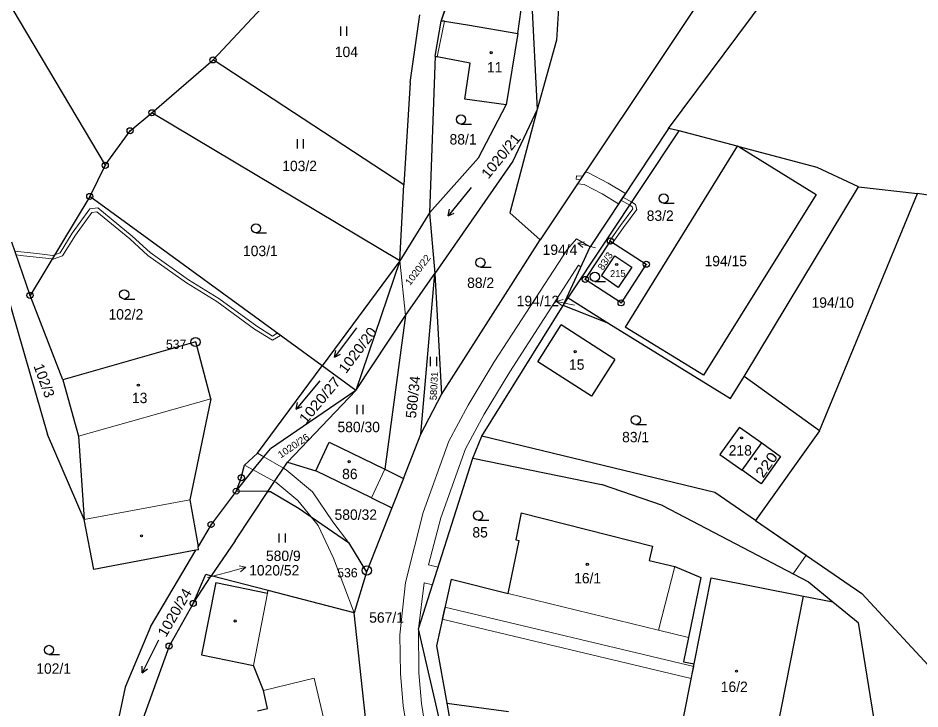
# Model space of a CAD drawing. Extents: x -601131 to -597152, y -1058536 to -1055911.
# Drawn here: x -599499.1 to -599351.3, y -1056861.6 to -1056748.4 of the extents above; entities that cross this region are included whole.
import ezdxf
from ezdxf.enums import TextEntityAlignment as Align

# ---------------------------------------------------------------- set-up
doc = ezdxf.new("R2010")
doc.units = 0
doc.header["$LTSCALE"] = 0.68
for name, color, linetype, lineweight in [('1', 7, 'Continuous', 25), ('13', 7, 'Continuous', 13), ('3', 7, 'Continuous', 25), ('4', 7, 'Continuous', 13), ('5', 7, 'Continuous', 25), ('7', 7, 'Continuous', 13), ('8', 7, 'Continuous', 25)]:
    doc.layers.add(name, color=color, linetype=linetype, lineweight=lineweight)
doc.layers.add('2', color=7, linetype='Continuous')

msp = doc.modelspace()

# ---------------------------------------------------------------- linework, layer by layer
at = {"layer": '1'}
for p, q in [((-599551.94, -1056659.38), (-599484.78, -1056772.53)), ((-599371.62, -1056721.87), (-599413.52, -1056784.73)), ((-599429.72, -1056748.92), (-599425.35, -1056734.91)), ((-599417.21, -1056750.96), (-599415.29, -1056737.38)), ((-599415.29, -1056737.38), (-599414.02, -1056763.41)), ((-599467.12, -1056755.26), (-599452.95, -1056740.08)), ((-599392.52, -1056766.52), (-599372.87, -1056740.17)), ((-599429.72, -1056748.92), (-599427.64, -1056742.94)), ((-599410.27, -1056742.24), (-599410.86, -1056752.01)), ((-599434.8, -1056758.96), (-599433.23, -1056747.88)), ((-599430.75, -1056754.64), (-599429.72, -1056748.92)), ((-599429.22, -1056748.92), (-599429.72, -1056748.92)), ((-599429.22, -1056748.92), (-599425.44, -1056749.51)), ((-599425.44, -1056749.51), (-599417.21, -1056750.96)), ((-599417.21, -1056750.96), (-599419.08, -1056762.64)), ((-599410.86, -1056752.01), (-599414.02, -1056763.41)), ((-599477.13, -1056763.92), (-599467.12, -1056755.26)), ((-599435.85, -1056775.73), (-599467.12, -1056755.26)), ((-599430.75, -1056754.64), (-599431.65, -1056780.31)), ((-599430.75, -1056754.64), (-599430.42, -1056754.74)), ((-599425, -1056755.8), (-599430.42, -1056754.74)), ((-599425.85, -1056761.7), (-599425, -1056755.8)), ((-599434.8, -1056758.96), (-599435.85, -1056775.73)), ((-599419.08, -1056762.64), (-599425.85, -1056761.7)), ((-599423.64, -1056771.32), (-599419.08, -1056762.64)), ((-599480.7, -1056766.87), (-599477.13, -1056763.92)), ((-599436.52, -1056788.17), (-599477.13, -1056763.92)), ((-599414.02, -1056763.41), (-599418.48, -1056780.32)), ((-599414.02, -1056763.41), (-599418.03, -1056771.83)), ((-599484.78, -1056772.53), (-599480.7, -1056766.87)), ((-599408.96, -1056794.27), (-599390.76, -1056766.89)), ((-599392.52, -1056766.52), (-599405.35, -1056785.88)), ((-599390.76, -1056766.89), (-599392.52, -1056766.52)), ((-599381.23, -1056769.41), (-599399.61, -1056799.07)), ((-599380.92, -1056769.49), (-599368.31, -1056777.29)), ((-599368.15, -1056772.87), (-599380.92, -1056769.49)), ((-599431.65, -1056780.31), (-599423.64, -1056771.32)), ((-599484.78, -1056772.53), (-599487.31, -1056777.64)), ((-599418.03, -1056771.83), (-599430.78, -1056790.24)), ((-599361.35, -1056776.07), (-599368.15, -1056772.87)), ((-599436.52, -1056788.17), (-599435.85, -1056775.73)), ((-599368.31, -1056777.29), (-599386.76, -1056806.92)), ((-599380.09, -1056807.12), (-599361.35, -1056776.07)), ((-599367.78, -1056816.02), (-599351.73, -1056777.15)), ((-599361.35, -1056776.07), (-599351.73, -1056777.15)), ((-599327.76, -1056781.06), (-599351.73, -1056777.15)), ((-599487.31, -1056777.64), (-599497.1, -1056793.85)), ((-599449.25, -1056805.4), (-599487.31, -1056777.64)), ((-599431.65, -1056780.31), (-599436.52, -1056788.17)), ((-599431.65, -1056780.31), (-599430.78, -1056790.24)), ((-599413.52, -1056784.73), (-599418.48, -1056780.32)), ((-599429.67, -1056810.07), (-599413.52, -1056784.73)), ((-599497.1, -1056793.85), (-599500.08, -1056785.1)), ((-599409.73, -1056795.49), (-599405.35, -1056785.88)), ((-599406.13, -1056791.23), (-599402.01, -1056784.94)), ((-599402.01, -1056784.94), (-599396.14, -1056788.74)), ((-599436.52, -1056788.17), (-599449.25, -1056805.4)), ((-599436.52, -1056788.17), (-599443.7, -1056809.45)), ((-599398.5, -1056789.24), (-599400.72, -1056792.53)), ((-599396.14, -1056788.74), (-599400.26, -1056795.07)), ((-599435.58, -1056797.13), (-599430.78, -1056790.24)), ((-599433.05, -1056816.57), (-599430.78, -1056790.24)), ((-599430.78, -1056790.24), (-599429.67, -1056810.07)), ((-599400.26, -1056795.07), (-599406.13, -1056791.23)), ((-599501.07, -1056792.92), (-599494.25, -1056816.67)), ((-599491.72, -1056807.67), (-599497.1, -1056793.85)), ((-599409.73, -1056795.49), (-599408.96, -1056794.27)), ((-599408.96, -1056794.27), (-599402.25, -1056798.43)), ((-599423.06, -1056816.9), (-599409.73, -1056795.49)), ((-599402.25, -1056798.43), (-599409.73, -1056795.49)), ((-599443.7, -1056809.45), (-599435.58, -1056797.13)), ((-599435.58, -1056797.13), (-599439, -1056822.33)), ((-599413.91, -1056804.75), (-599410.1, -1056798.68)), ((-599401.3, -1056804.33), (-599410.1, -1056798.68)), ((-599402.25, -1056798.43), (-599382.36, -1056810.74)), ((-599386.76, -1056806.92), (-599399.61, -1056799.07)), ((-599469.95, -1056801.48), (-599491.72, -1056807.67)), ((-599467.5, -1056810.78), (-599469.95, -1056801.48)), ((-599459.81, -1056819.7), (-599449.25, -1056805.4)), ((-599443.7, -1056809.45), (-599449.25, -1056805.4)), ((-599405.13, -1056810.34), (-599413.91, -1056804.75)), ((-599401.3, -1056804.33), (-599405.13, -1056810.34)), ((-599491.72, -1056807.67), (-599489.16, -1056816.94)), ((-599382.36, -1056810.74), (-599380.09, -1056807.12)), ((-599367.78, -1056816.02), (-599380.09, -1056807.12)), ((-599443.7, -1056809.45), (-599457.68, -1056818.97)), ((-599443.7, -1056809.45), (-599454.94, -1056821.19)), ((-599467.5, -1056810.78), (-599470.92, -1056827.35)), ((-599433.05, -1056816.57), (-599429.67, -1056810.07)), ((-599380.86, -1056815.42), (-599384.07, -1056819.9)), ((-599380.86, -1056815.42), (-599377.23, -1056818.03)), ((-599488.25, -1056830.58), (-599494.25, -1056816.67)), ((-599489.16, -1056816.94), (-599488.25, -1056830.58)), ((-599435.92, -1056823.84), (-599433.05, -1056816.57)), ((-599424.56, -1056820.53), (-599423.06, -1056816.9)), ((-599384.89, -1056826.15), (-599423.06, -1056816.9)), ((-599367.78, -1056816.02), (-599378.25, -1056830.74)), ((-599450.26, -1056822.59), (-599448.07, -1056817.88)), ((-599448.07, -1056817.88), (-599439, -1056822.33)), ((-599377.23, -1056818.03), (-599374.16, -1056820.24)), ((-599461.96, -1056821.68), (-599459.81, -1056819.7)), ((-599460.52, -1056822.46), (-599458.77, -1056820.31)), ((-599458.77, -1056820.31), (-599457.68, -1056818.97)), ((-599384.07, -1056819.9), (-599380.42, -1056822.5)), ((-599462.49, -1056823.71), (-599461.96, -1056821.68)), ((-599455.6, -1056822.18), (-599454.94, -1056821.19)), ((-599454.94, -1056821.19), (-599450.26, -1056822.59)), ((-599433.46, -1056848.51), (-599424.56, -1056820.53)), ((-599424.56, -1056820.53), (-599403.47, -1056824.84)), ((-599463.33, -1056825.93), (-599460.52, -1056822.46)), ((-599457.04, -1056824.35), (-599455.6, -1056822.18)), ((-599441.15, -1056827.03), (-599450.26, -1056822.59)), ((-599439, -1056822.33), (-599435.92, -1056823.84)), ((-599462.49, -1056823.71), (-599463.33, -1056825.93)), ((-599458.14, -1056826), (-599457.04, -1056824.35)), ((-599435.92, -1056823.84), (-599437.83, -1056828.65)), ((-599463.33, -1056825.93), (-599467.43, -1056831.39)), ((-599463.51, -1056834.09), (-599458.14, -1056826)), ((-599458.14, -1056826), (-599463.33, -1056825.93)), ((-599458.14, -1056826), (-599457.68, -1056826.01)), ((-599457.68, -1056826.01), (-599453.02, -1056828.76)), ((-599393.47, -1056828.27), (-599403.47, -1056824.84)), ((-599378.25, -1056830.74), (-599384.89, -1056826.15)), ((-599470.92, -1056827.35), (-599469.58, -1056835.02)), ((-599441.15, -1056827.03), (-599437.83, -1056828.65)), ((-599453.02, -1056828.76), (-599451.06, -1056830.11)), ((-599437.83, -1056828.65), (-599442, -1056839.21)), ((-599393.47, -1056828.27), (-599369.55, -1056840.81)), ((-599486.66, -1056838.75), (-599488.25, -1056830.58)), ((-599451.06, -1056830.11), (-599444.93, -1056834.36)), ((-599416.62, -1056829.48), (-599417.51, -1056833.91)), ((-599416.62, -1056829.48), (-599395.11, -1056834.93)), ((-599467.43, -1056831.39), (-599469.58, -1056835.02)), ((-599378.25, -1056830.74), (-599360.82, -1056842.71)), ((-599469.49, -1056835.54), (-599469.58, -1056835.02)), ((-599463.51, -1056834.09), (-599467.42, -1056839.8)), ((-599444.93, -1056834.36), (-599442, -1056839.21)), ((-599418.78, -1056842.69), (-599416.95, -1056834.02)), ((-599417.51, -1056833.91), (-599416.95, -1056834.02)), ((-599395.11, -1056834.93), (-599395.66, -1056837.27)), ((-599469.94, -1056835.62), (-599486.66, -1056838.75)), ((-599477.37, -1056848.16), (-599469.94, -1056835.62)), ((-599469.49, -1056835.54), (-599469.94, -1056835.62)), ((-599395.66, -1056837.27), (-599391.44, -1056838.26)), ((-599470.36, -1056844.32), (-599468.28, -1056839.51)), ((-599468.28, -1056839.51), (-599467.42, -1056839.8)), ((-599442, -1056839.21), (-599443.98, -1056845.84)), ((-599391.44, -1056838.26), (-599387.21, -1056840.08)), ((-599470.36, -1056844.32), (-599467.42, -1056839.8)), ((-599466.66, -1056840.89), (-599468.99, -1056852.74)), ((-599458.1, -1056842.2), (-599467.42, -1056839.8)), ((-599466.66, -1056840.89), (-599458.19, -1056842.66)), ((-599428.13, -1056840.35), (-599430.53, -1056851.27)), ((-599428.13, -1056840.35), (-599418.78, -1056842.69)), ((-599387.21, -1056840.08), (-599389.22, -1056849.88)), ((-599388.28, -1056854.23), (-599385.49, -1056840.15)), ((-599385.49, -1056840.15), (-599370.36, -1056843.12)), ((-599369.55, -1056840.81), (-599365.59, -1056844.06)), ((-599458.19, -1056842.66), (-599458.1, -1056842.2)), ((-599443.98, -1056845.84), (-599458.1, -1056842.2)), ((-599375.51, -1056869.1), (-599370.36, -1056843.12)), ((-599345.66, -1056859.14), (-599360.82, -1056842.71)), ((-599470.36, -1056844.32), (-599474.31, -1056851.31)), ((-599441.71, -1056867.16), (-599443.98, -1056845.84)), ((-599477.37, -1056848.16), (-599481.51, -1056858.06)), ((-599361.42, -1056847.47), (-599358.35, -1056866.66)), ((-599420.11, -1056905.82), (-599433.46, -1056848.51)), ((-599389.22, -1056849.88), (-599390.05, -1056853.89)), ((-599474.31, -1056851.31), (-599479.03, -1056864.47)), ((-599430.53, -1056851.27), (-599428.83, -1056860.65)), ((-599468.99, -1056852.74), (-599460.51, -1056854.48)), ((-599390.58, -1056865.84), (-599388.28, -1056854.23)), ((-599390.05, -1056853.89), (-599388.28, -1056854.23)), ((-599458.83, -1056858.57), (-599460.51, -1056854.48)), ((-599481.51, -1056858.06), (-599483.14, -1056865.86)), ((-599458.17, -1056861.55), (-599458.83, -1056858.57)), ((-599459.85, -1056861.92), (-599458.17, -1056861.55)), ((-599428.83, -1056860.65), (-599418.74, -1056862.02)), ((-599428.83, -1056860.65), (-599426.94, -1056871.04))]:
    msp.add_line(p, q, dxfattribs=at)
for points in [[(-599380.92, -1056769.49), (-599381.23, -1056769.41), (-599390.76, -1056766.89)], [(-599400.72, -1056792.53), (-599403.49, -1056790.67), (-599401.28, -1056787.37), (-599398.5, -1056789.24)], [(-599374.16, -1056820.24), (-599377.34, -1056824.7), (-599380.42, -1056822.5), (-599377.23, -1056818.03)], [(-599370.36, -1056843.12), (-599365.59, -1056844.06), (-599361.42, -1056847.47)]]:
    msp.add_lwpolyline(points, dxfattribs=at)
at = {"layer": '13'}
for points in [[(-599407.65, -1056774.83), (-599406.97, -1056774.9), (-599406.59, -1056774.33), (-599407.59, -1056774.23)], [(-599406.15, -1056773.67), (-599406.59, -1056774.33), (-599406.97, -1056774.9), (-599407.41, -1056775.56), (-599406.32, -1056775.67), (-599403.37, -1056777.19), (-599400.68, -1056778.83), (-599400.29, -1056778.25), (-599399.96, -1056777.75), (-599399.57, -1056777.16), (-599402.39, -1056775.45), (-599405.74, -1056773.71)], [(-599399.88, -1056782.75), (-599397.69, -1056779.76), (-599397.92, -1056778.93), (-599398.53, -1056778.58), (-599399.96, -1056777.75), (-599400.29, -1056778.25), (-599398.86, -1056779.08), (-599398.44, -1056779.33), (-599398.35, -1056779.64), (-599400.36, -1056782.39), (-599402.18, -1056784.96), (-599402.08, -1056785.05), (-599402.01, -1056784.94), (-599401.61, -1056785.2)], [(-599402.03, -1056785.43), (-599401.86, -1056785.24), (-599401.73, -1056785.36), (-599401.61, -1056785.2), (-599402.01, -1056784.94), (-599402.08, -1056785.05), (-599402.22, -1056785.26)], [(-599423.06, -1056816.9), (-599424.56, -1056820.53), (-599403.47, -1056824.84), (-599393.47, -1056828.27), (-599372.06, -1056839.49), (-599369.96, -1056836.43), (-599378.25, -1056830.74), (-599384.89, -1056826.15)], [(-599429.13, -1056844.92), (-599429.56, -1056846.88), (-599388.76, -1056856.63), (-599388.37, -1056854.67)]]:
    msp.add_lwpolyline(points, close=True, dxfattribs=at)
for points in [[(-599499.36, -1056787.22), (-599498.64, -1056787.29), (-599496.07, -1056787.6), (-599493.49, -1056787.88), (-599493.3, -1056787.91), (-599491.77, -1056787.36), (-599489.67, -1056784), (-599486.95, -1056780.25), (-599486.16, -1056780.14), (-599480.76, -1056784.6), (-599477.81, -1056787.3), (-599471.48, -1056791.81), (-599466.49, -1056794.86), (-599460.31, -1056799.4), (-599457.36, -1056801.21), (-599456.09, -1056800.41), (-599456.61, -1056800.03), (-599457.36, -1056800.51), (-599459.97, -1056798.9), (-599466.15, -1056794.36), (-599471.14, -1056791.31), (-599477.43, -1056786.84), (-599480.36, -1056784.14), (-599485.98, -1056779.5), (-599487.29, -1056779.69), (-599490.17, -1056783.66), (-599492.17, -1056786.86), (-599493.08, -1056787.19), (-599493.38, -1056787.29), (-599496.01, -1056787), (-599498.58, -1056786.69), (-599499.57, -1056786.59)], [(-599431.63, -1056868.93), (-599432.99, -1056860.71), (-599433.42, -1056855.68), (-599433.46, -1056848.51), (-599432.51, -1056840.94), (-599431.15, -1056841.26), (-599430.24, -1056838.4), (-599431.81, -1056838.02), (-599429.82, -1056830.3), (-599425.77, -1056818.98), (-599422.72, -1056813.3), (-599418.52, -1056806.35), (-599407.24, -1056788.92), (-599406.85, -1056789.18), (-599405.35, -1056785.88), (-599407.59, -1056784.59), (-599409.06, -1056786.25), (-599421.06, -1056804.76), (-599425.32, -1056811.82), (-599428.51, -1056817.76), (-599432.69, -1056829.41), (-599435.59, -1056840.9), (-599436.51, -1056849.45), (-599436.42, -1056855.83), (-599435.97, -1056861.08), (-599434.58, -1056869.5)]]:
    msp.add_lwpolyline(points, dxfattribs=at)
at = {"layer": '3'}
for p, q in [((-599446.181, -1056751.3), (-599446.181, -1056749.8)), ((-599445.18, -1056751.3), (-599445.18, -1056749.8)), ((-599426.503, -1056765.78), (-599424.753, -1056765.78)), ((-599453.301, -1056769.77), (-599453.301, -1056768.27)), ((-599452.3, -1056769.77), (-599452.3, -1056768.27)), ((-599393.303, -1056778.73), (-599391.553, -1056778.73)), ((-599428.595, -1056780.809), (-599428.37, -1056779.734)), ((-599460.083, -1056783.6), (-599458.333, -1056783.6)), ((-599423.313, -1056789.22), (-599421.563, -1056789.22)), ((-599404.573, -1056791.56), (-599402.823, -1056791.56)), ((-599481.683, -1056794.44), (-599479.933, -1056794.44)), ((-599447.213, -1056803.954), (-599447.025, -1056802.872)), ((-599431.471, -1056805.43), (-599431.471, -1056803.93)), ((-599430.47, -1056805.43), (-599430.47, -1056803.93)), ((-599453.506, -1056812.466), (-599453.262, -1056811.395)), ((-599443.511, -1056813.29), (-599443.511, -1056811.79)), ((-599442.51, -1056813.29), (-599442.51, -1056811.79)), ((-599397.853, -1056815.01), (-599396.103, -1056815.01)), ((-599423.693, -1056830.67), (-599421.943, -1056830.67)), ((-599456.271, -1056834.34), (-599456.271, -1056832.84)), ((-599455.27, -1056834.34), (-599455.27, -1056832.84)), ((-599494.003, -1056852.69), (-599492.253, -1056852.69)), ((-599478.71, -1056855.718), (-599478.733, -1056854.62))]:
    msp.add_line(p, q, dxfattribs=at)
for points in [[(-599424.819, -1056776.146), (-599428.595, -1056780.809), (-599427.591, -1056780.366)], [(-599443.602, -1056799.163), (-599447.213, -1056803.954), (-599446.224, -1056803.476)], [(-599449.649, -1056807.869), (-599453.506, -1056812.466), (-599452.494, -1056812.04)], [(-599476.08, -1056850.325), (-599478.71, -1056855.718), (-599477.831, -1056855.06)]]:
    msp.add_lwpolyline(points, dxfattribs=at)
for centre in [(-599426.5029, -1056765.0298), (-599393.3029, -1056777.9798), (-599460.0829, -1056782.8498), (-599423.3129, -1056788.4698), (-599404.5729, -1056790.8098), (-599481.6829, -1056793.6898), (-599397.8529, -1056814.2598), (-599423.6929, -1056829.9198), (-599494.0029, -1056851.9398)]:
    msp.add_circle(centre, 0.75, dxfattribs=at)
at = {"layer": '4'}
for p, q in [((-599430.42, -1056754.74), (-599429.22, -1056748.92)), ((-599381.23, -1056769.41), (-599381.18, -1056769.32)), ((-599381.18, -1056769.32), (-599380.92, -1056769.49)), ((-599435.58, -1056797.13), (-599436.52, -1056788.17)), ((-599489.16, -1056816.94), (-599467.5, -1056810.78)), ((-599458.77, -1056820.31), (-599459.81, -1056819.7)), ((-599455.6, -1056822.18), (-599458.77, -1056820.31)), ((-599460.52, -1056822.46), (-599461.96, -1056821.68)), ((-599457.04, -1056824.35), (-599460.52, -1056822.46)), ((-599455.15, -1056822.44), (-599455.6, -1056822.18)), ((-599450.8, -1056826.05), (-599455.15, -1056822.44)), ((-599441.15, -1056827.03), (-599439, -1056822.33)), ((-599456.81, -1056824.47), (-599457.04, -1056824.35)), ((-599456.81, -1056824.47), (-599453.24, -1056827.48)), ((-599447.47, -1056830.97), (-599450.8, -1056826.05)), ((-599488.25, -1056830.58), (-599470.92, -1056827.35)), ((-599453.24, -1056827.48), (-599451.06, -1056830.11)), ((-599451.06, -1056830.11), (-599449.87, -1056831.56)), ((-599449.87, -1056831.56), (-599447.39, -1056836.89)), ((-599444.93, -1056834.36), (-599447.47, -1056830.97)), ((-599447.39, -1056836.89), (-599443.98, -1056845.84)), ((-599394.15, -1056848.68), (-599391.44, -1056838.26)), ((-599460.51, -1056854.48), (-599458.19, -1056842.66)), ((-599418.78, -1056842.69), (-599394.15, -1056848.68)), ((-599394.15, -1056848.68), (-599389.22, -1056849.88)), ((-599450.55, -1056856.58), (-599458.83, -1056858.57)), ((-599447.77, -1056868.39), (-599450.55, -1056856.58))]:
    msp.add_line(p, q, dxfattribs=at)
at = {"layer": '5'}
for centre in [(-599421.5468, -1056754.0692), (-599400.9868, -1056788.7792), (-599407.7868, -1056803.0692), (-599479.3468, -1056808.5492), (-599380.5268, -1056817.1892), (-599444.8068, -1056821.0992), (-599378.2468, -1056820.6292), (-599478.8368, -1056833.2492), (-599405.8068, -1056837.9192), (-599463.4968, -1056847.1992), (-599381.3668, -1056855.4192)]:
    msp.add_circle(centre, 0.175, dxfattribs=at)
at = {"layer": '7'}
for p, q in [((-599407.359, -1056785.283), (-599406.521, -1056786.026)), ((-599410.855, -1056794.826), (-599409.98, -1056795.524)), ((-599461.761, -1056838.403), (-599462.858, -1056838.179))]:
    msp.add_line(p, q, dxfattribs=at)
for points in [[(-599404.46, -1056786.06), (-599407.359, -1056785.283), (-599406.262, -1056785.059)], [(-599407.92, -1056795.45), (-599410.855, -1056794.826), (-599409.772, -1056794.544)], [(-599468.02, -1056840.07), (-599464.66, -1056839.18), (-599461.761, -1056838.403), (-599462.599, -1056839.146)]]:
    msp.add_lwpolyline(points, dxfattribs=at)
at = {"layer": '8'}
for centre, radius in [((-599467.12, -1056755.2599), 0.5), ((-599467.12, -1056755.2599), 0.0303), ((-599477.13, -1056763.9199), 0.5), ((-599477.13, -1056763.9199), 0.0303), ((-599480.7, -1056766.8699), 0.5), ((-599480.7, -1056766.8699), 0.0303), ((-599484.78, -1056772.5299), 0.5), ((-599484.78, -1056772.5299), 0.0303), ((-599487.31, -1056777.6399), 0.5), ((-599487.31, -1056777.6399), 0.0303), ((-599402.01, -1056784.9399), 0.5), ((-599402.01, -1056784.9399), 0.0303), ((-599396.14, -1056788.7399), 0.5), ((-599396.14, -1056788.7399), 0.0303), ((-599406.13, -1056791.2299), 0.5), ((-599406.13, -1056791.2299), 0.0303), ((-599497.1, -1056793.8499), 0.5), ((-599497.1, -1056793.8499), 0.0303), ((-599400.26, -1056795.0699), 0.5), ((-599400.26, -1056795.0699), 0.0303), ((-599469.99, -1056801.4998), 0.75), ((-599469.99, -1056801.4998), 0.03), ((-599462.49, -1056823.7099), 0.5), ((-599462.49, -1056823.7099), 0.0303), ((-599463.33, -1056825.9299), 0.5), ((-599463.33, -1056825.9299), 0.0303), ((-599467.43, -1056831.3899), 0.5), ((-599467.43, -1056831.3899), 0.0303), ((-599441.93, -1056838.9298), 0.75), ((-599441.93, -1056838.9298), 0.03), ((-599470.36, -1056844.3199), 0.5), ((-599470.36, -1056844.3199), 0.0303), ((-599474.31, -1056851.3099), 0.5), ((-599474.31, -1056851.3099), 0.0303)]:
    msp.add_circle(centre, radius, dxfattribs=at)

# ---------------------------------------------------------------- texts
at = {"layer": '2'}
for s, p in [('104', (-599447.17, -1056754.795)), ('11', (-599422.24, -1056757.314)), ('88/1', (-599428.37, -1056769.125)), ('103/2', (-599455.78, -1056773.485)), ('83/2', (-599396.07, -1056781.635)), ('103/1', (-599462.21, -1056787.415)), ('194/4', (-599413.12, -1056787.215)), ('194/15', (-599386.6, -1056789.064)), ('88/2', (-599425.49, -1056792.635)), ('194/12', (-599417.37, -1056795.615)), ('194/10', (-599369.07, -1056795.875)), ('102/2', (-599484.24, -1056797.804)), ('15', (-599408.8, -1056806.035)), ('13', (-599480.4, -1056811.505)), ('580/30', (-599446.73, -1056816.265)), ('83/1', (-599400.1, -1056817.915)), ('86', (-599445.97, -1056823.955)), ('580/32', (-599447.21, -1056830.625)), ('85', (-599424.63, -1056833.515)), ('580/9', (-599458.45, -1056837.375)), ('1020/52', (-599461.2, -1056839.745)), ('16/1', (-599407.96, -1056841.035)), ('567/1', (-599441.53, -1056847.485)), ('102/1', (-599496.08, -1056855.844)), ('16/2', (-599383.94, -1056858.834))]:
    msp.add_text(s, height=1.7, dxfattribs=at).set_placement(p)
for s, height, rotation, width, p in [('1020/21', 1.7, 51, 1.05, (-599422.009, -1056774.877)), ('1020/22', 1.14, 53, 1.05, (-599434.842, -1056792.321)), ('83/3', 1.139, 57, 1.05, (-599403.231, -1056789.835)), ('1020/20', 1.7, 53, 1.05, (-599445.35, -1056806.775)), ('1020/27', 1.7, 50, 1.1, (-599451.884, -1056815.023)), ('1020/26', 1.14, 34, 1.05, (-599456.03, -1056820.586)), ('1020/24', 1.7, 60, 1.05, (-599474.831, -1056849.982))]:
    msp.add_text(s, height=height, rotation=rotation, dxfattribs=dict(at, width=width)).set_placement(p)
for s, height, rotation, p in [('215', 1.139, 1, (-599402.065, -1056790.864)), ('102/3', 1.7, 290, (-599496.549, -1056805.435)), ('580/31', 1.14, 87, (-599430.485, -1056811.044)), ('580/34', 1.7, 84, (-599433.877, -1056814.054))]:
    msp.add_text(s, height=height, rotation=rotation, dxfattribs=at).set_placement(p)
msp.add_text('218', height=1.7, dxfattribs=at).set_placement((-599380.739, -1056820.094), align=Align.CENTER)
at = {"layer": '2', "width": 1.15}
msp.add_text('220', height=1.7, rotation=55, dxfattribs=at).set_placement((-599375.7474, -1056822.0945), align=Align.CENTER)
at = {"layer": '8'}
for s, p in [('537', (-599471.489, -1056802.617)), ('536', (-599443.429, -1056840.047))]:
    msp.add_text(s, height=1.5, dxfattribs=at).set_placement(p, align=Align.RIGHT)

doc.saveas('drawing.dxf')
